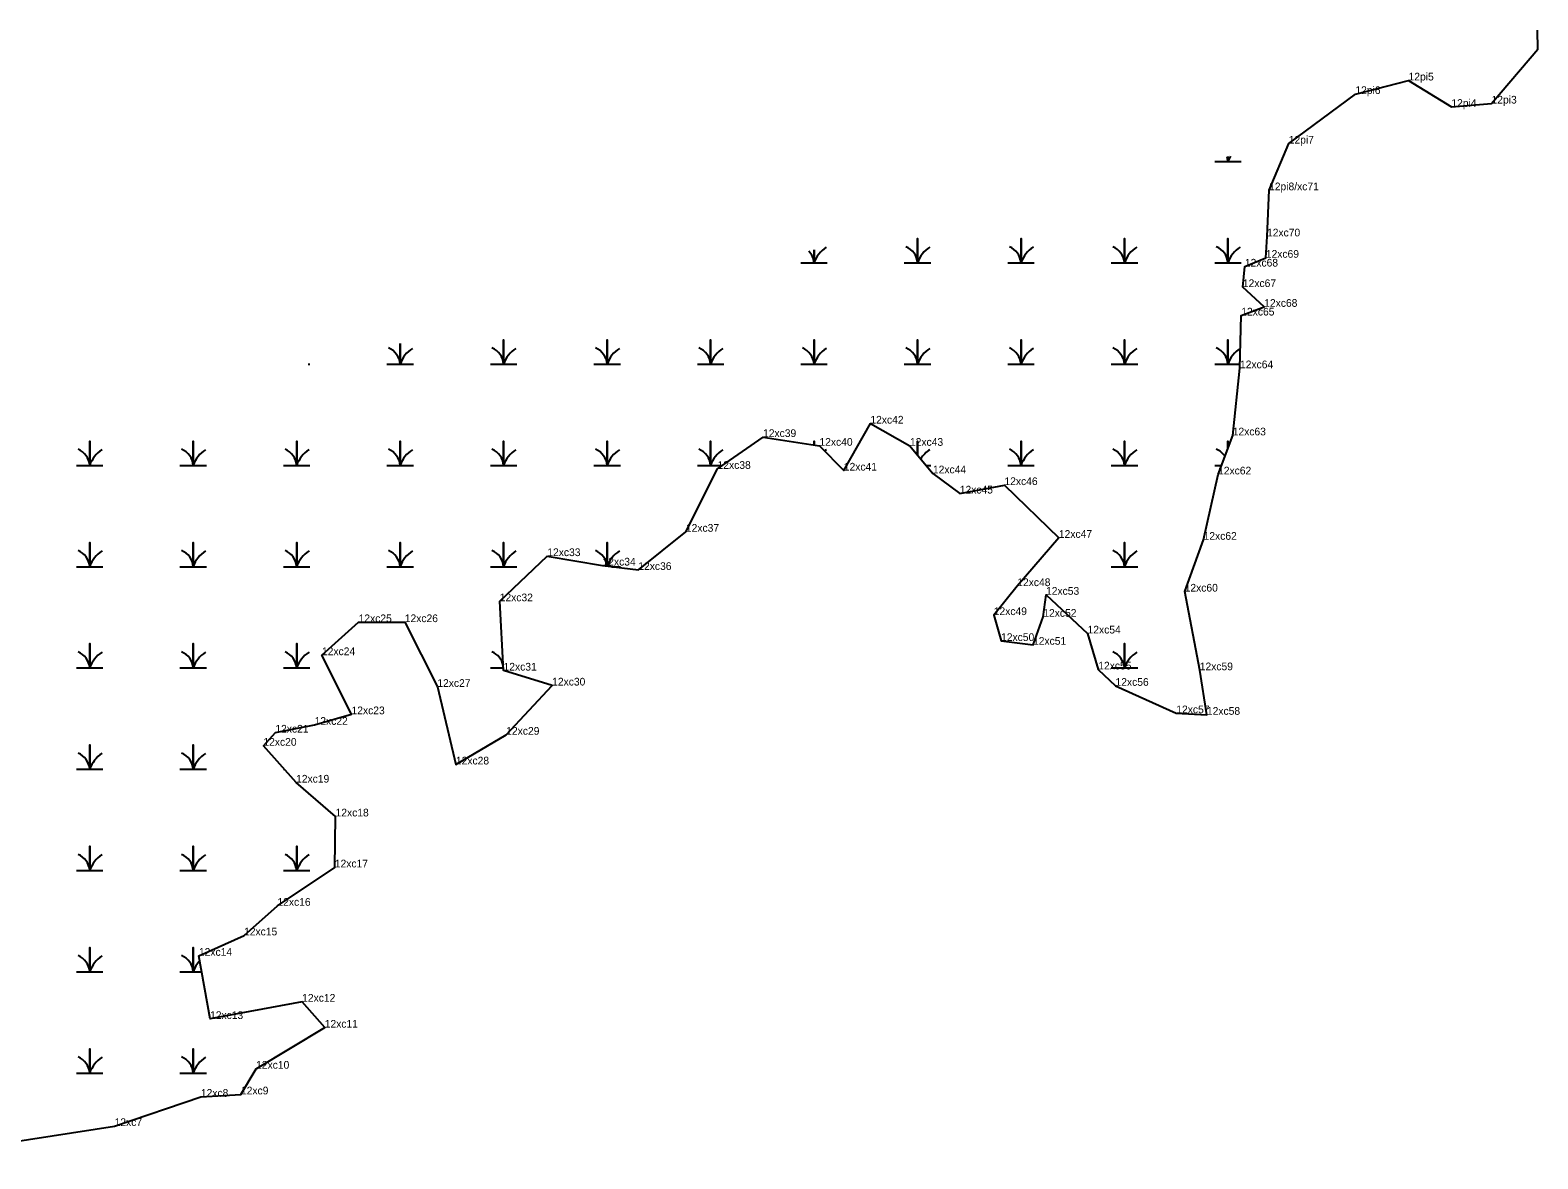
# Model space of a CAD drawing. Extents: x 2072529 to 2268796, y 436423 to 470406.
# Drawn here: x 2230922 to 2231902, y 451635 to 452369 of the extents above; entities that cross this region are included whole.
import ezdxf

# ---------------------------------------------------------------- set-up
doc = ezdxf.new("R2010")
doc.units = 0
for name, color, linetype in [('Exist Environmental Wetland Boundary', 7, 'Continuous'), ('Exist Environmental Wetland Boundary Cogo Comment', 7, 'Continuous'), ('Exist Hydro Swamp or Marsh', 7, 'Continuous'), ('Old_Level_20', 7, 'Continuous')]:
    doc.layers.add(name, color=color, linetype=linetype)

msp = doc.modelspace()

# ---------------------------------------------------------------- linework, layer by layer
at = {"layer": 'Exist Environmental Wetland Boundary'}
msp.add_lwpolyline([(2230840.12, 451635.35), (2230977.33, 451656.68), (2231033.38, 451675.67), (2231059.44, 451677.21), (2231069.29, 451693.9), (2231113.89, 451720.58), (2231099.21, 451737.45), (2231039.34, 451726.21), (2231032.11, 451767.28), (2231061.44, 451780.53), (2231083.15, 451799.77), (2231120.44, 451824.7), (2231120.92, 451857.81), (2231095.26, 451879.8), (2231074.02, 451903.73), (2231081.79, 451912.28), (2231107.3, 451917.34), (2231131.3, 451924.2), (2231112.09, 451962.59), (2231135.92, 451984.02), (2231165.9, 451984.05), (2231187.06, 451941.99), (2231199.13, 451891.58), (2231231.84, 451910.9), (2231261.68, 451942.87), (2231230.1, 451952.58), (2231227.61, 451997.6), (2231258.54, 452026.96), (2231294.4, 452020.83), (2231317.69, 452017.96), (2231348.61, 452042.78), (2231369.19, 452083.62), (2231398.74, 452104.33), (2231435.4, 452098.64), (2231451.23, 452082.52), (2231468.5, 452113.06), (2231494.24, 452098.62), (2231509.15, 452080.73), (2231526.59, 452067.62), (2231555.64, 452073.11), (2231591.01, 452038.81), (2231563.97, 452007.45), (2231548.69, 451988.63), (2231553.44, 451971.8), (2231574.2, 451969.37), (2231580.88, 451987.54), (2231582.65, 452001.84), (2231609.65, 451976.67), (2231616.61, 451953.3), (2231627.81, 451942.68), (2231667.33, 451924.84), (2231687.23, 451923.86), (2231682.58, 451952.79), (2231672.76, 452003.9), (2231685.07, 452037.55), (2231694.47, 452080.01), (2231704, 452105.38), (2231708.71, 452148.99), (2231709.55, 452183.27), (2231724.47, 452188.92), (2231710.6, 452201.75), (2231711.89, 452215.08), (2231725.51, 452220.79), (2231726.27, 452234.66), (2231727.61, 452264.64), (2231740.4, 452294.96), (2231783.7, 452327.18), (2231818.27, 452335.98), (2231846.1, 452318.82), (2231872.2, 452320.98), (2231902.29, 452356.34), (2231902.14, 452368.66)], dxfattribs=at)
at = {"layer": 'Exist Hydro Swamp or Marsh'}
for points in [[(2231692.3, 452283.29), (2231700.9, 452283.29), (2231700.9, 452286.5)], [(2231700.9, 452286.5), (2231700.9, 452283.29), (2231709.5, 452283.29)], [(2231490.55, 452217.49), (2231499.15, 452217.49), (2231499.15, 452233.27), (2231499.15, 452217.49), (2231507.75, 452217.49)], [(2231557.8, 452217.49), (2231566.4, 452217.49), (2231566.4, 452233.27), (2231566.4, 452217.49), (2231575, 452217.49)], [(2231625.05, 452217.49), (2231633.65, 452217.49), (2231633.65, 452233.27), (2231633.65, 452217.49), (2231642.25, 452217.49)], [(2231692.3, 452217.49), (2231700.9, 452217.49), (2231700.9, 452233.27), (2231700.9, 452217.49), (2231709.5, 452217.49)], [(2231423.3, 452217.49), (2231431.9, 452217.49), (2231431.9, 452225.84)], [(2231431.9, 452225.84), (2231431.9, 452217.49), (2231440.5, 452217.49)], [(2231154.3, 452151.69), (2231162.9, 452151.69), (2231162.9, 452165.17)], [(2231162.9, 452165.17), (2231162.9, 452151.69), (2231171.5, 452151.69)], [(2231221.55, 452151.69), (2231230.15, 452151.69), (2231230.15, 452167.47), (2231230.15, 452151.69), (2231238.75, 452151.69)], [(2231288.8, 452151.69), (2231297.4, 452151.69), (2231297.4, 452167.47), (2231297.4, 452151.69), (2231306, 452151.69)], [(2231356.05, 452151.69), (2231364.65, 452151.69), (2231364.65, 452167.47), (2231364.65, 452151.69), (2231373.25, 452151.69)], [(2231423.3, 452151.69), (2231431.9, 452151.69), (2231431.9, 452167.47), (2231431.9, 452151.69), (2231440.5, 452151.69)], [(2231490.55, 452151.69), (2231499.15, 452151.69), (2231499.15, 452167.47), (2231499.15, 452151.69), (2231507.75, 452151.69)], [(2231557.8, 452151.69), (2231566.4, 452151.69), (2231566.4, 452167.47), (2231566.4, 452151.69), (2231575, 452151.69)], [(2231625.05, 452151.69), (2231633.65, 452151.69), (2231633.65, 452167.47), (2231633.65, 452151.69), (2231642.25, 452151.69)], [(2231692.3, 452151.69), (2231700.9, 452151.69), (2231700.9, 452167.47), (2231700.9, 452151.69), (2231708.77, 452151.69)], [(2231103.12, 452151.69), (2231104.25, 452151.69)], [(2230952.55, 452085.89), (2230961.15, 452085.89), (2230961.15, 452101.67), (2230961.15, 452085.89), (2230969.75, 452085.89)], [(2231019.8, 452085.89), (2231028.4, 452085.89), (2231028.4, 452101.67), (2231028.4, 452085.89), (2231037, 452085.89)], [(2231087.05, 452085.89), (2231095.65, 452085.89), (2231095.65, 452101.67), (2231095.65, 452085.89), (2231104.25, 452085.89)], [(2231154.3, 452085.89), (2231162.9, 452085.89), (2231162.9, 452101.67), (2231162.9, 452085.89), (2231171.5, 452085.89)], [(2231221.55, 452085.89), (2231230.15, 452085.89), (2231230.15, 452101.67), (2231230.15, 452085.89), (2231238.75, 452085.89)], [(2231288.8, 452085.89), (2231297.4, 452085.89), (2231297.4, 452101.67), (2231297.4, 452085.89), (2231306, 452085.89)], [(2231356.05, 452085.89), (2231364.65, 452085.89), (2231364.65, 452101.67), (2231364.65, 452085.89), (2231372.43, 452085.89)], [(2231431.9, 452099.19), (2231431.9, 452101.67), (2231431.9, 452099.19)], [(2231499.15, 452092.73), (2231499.15, 452101.67), (2231499.15, 452092.73)], [(2231557.8, 452085.89), (2231566.4, 452085.89), (2231566.4, 452101.67), (2231566.4, 452085.89), (2231575, 452085.89)], [(2231625.05, 452085.89), (2231633.65, 452085.89), (2231633.65, 452101.67), (2231633.65, 452085.89), (2231642.25, 452085.89)], [(2231700.9, 452097.13), (2231700.9, 452101.67), (2231700.9, 452097.13)], [(2231504.85, 452085.89), (2231507.75, 452085.89)], [(2231692.3, 452085.89), (2231696.68, 452085.89)], [(2230952.55, 452020.09), (2230961.15, 452020.09), (2230961.15, 452035.87), (2230961.15, 452020.09), (2230969.75, 452020.09)], [(2231019.8, 452020.09), (2231028.4, 452020.09), (2231028.4, 452035.87), (2231028.4, 452020.09), (2231037, 452020.09)], [(2231087.05, 452020.09), (2231095.65, 452020.09), (2231095.65, 452035.87), (2231095.65, 452020.09), (2231104.25, 452020.09)], [(2231154.3, 452020.09), (2231162.9, 452020.09), (2231162.9, 452035.87), (2231162.9, 452020.09), (2231171.5, 452020.09)], [(2231221.55, 452020.09), (2231230.15, 452020.09), (2231230.15, 452035.87), (2231230.15, 452020.09), (2231238.75, 452020.09)], [(2231297.4, 452020.46), (2231297.4, 452035.87), (2231297.4, 452020.46)], [(2231625.05, 452020.09), (2231633.65, 452020.09), (2231633.65, 452035.87), (2231633.65, 452020.09), (2231642.25, 452020.09)], [(2231300.38, 452020.09), (2231306, 452020.09)], [(2231574.87, 452020.09), (2231575, 452020.09)], [(2230952.55, 451954.29), (2230961.15, 451954.29), (2230961.15, 451970.07), (2230961.15, 451954.29), (2230969.75, 451954.29)], [(2231019.8, 451954.29), (2231028.4, 451954.29), (2231028.4, 451970.07), (2231028.4, 451954.29), (2231037, 451954.29)], [(2231087.05, 451954.29), (2231095.65, 451954.29), (2231095.65, 451970.07), (2231095.65, 451954.29), (2231104.25, 451954.29)], [(2231625.05, 451954.29), (2231633.65, 451954.29), (2231633.65, 451970.07), (2231633.65, 451954.29), (2231642.25, 451954.29)], [(2231221.55, 451954.29), (2231230, 451954.29)], [(2230952.55, 451888.49), (2230961.15, 451888.49), (2230961.15, 451904.27), (2230961.15, 451888.49), (2230969.75, 451888.49)], [(2231019.8, 451888.49), (2231028.4, 451888.49), (2231028.4, 451904.27), (2231028.4, 451888.49), (2231037, 451888.49)], [(2231087.05, 451888.49), (2231087.54, 451888.49)], [(2230952.55, 451822.69), (2230961.15, 451822.69), (2230961.15, 451838.47), (2230961.15, 451822.69), (2230969.75, 451822.69)], [(2231019.8, 451822.69), (2231028.4, 451822.69), (2231028.4, 451838.47), (2231028.4, 451822.69), (2231037, 451822.69)], [(2231087.05, 451822.69), (2231095.65, 451822.69), (2231095.65, 451838.47), (2231095.65, 451822.69), (2231104.25, 451822.69)], [(2230952.55, 451756.89), (2230961.15, 451756.89), (2230961.15, 451772.67), (2230961.15, 451756.89), (2230969.75, 451756.89)], [(2231019.8, 451756.89), (2231028.4, 451756.89), (2231028.4, 451772.67), (2231028.4, 451756.89), (2231033.94, 451756.89)], [(2230952.55, 451691.09), (2230961.15, 451691.09), (2230961.15, 451706.87), (2230961.15, 451691.09), (2230969.75, 451691.09)], [(2231019.8, 451691.09), (2231028.4, 451691.09), (2231028.4, 451706.87), (2231028.4, 451691.09), (2231037, 451691.09)]]:
    msp.add_lwpolyline(points, dxfattribs=at)
for centre, radius, start, end in [((2231688.63, 452282.4), 12.3, 4.14034, 18.7832), ((2231719.14, 452277.23), 19.22, 149.91531, 161.62219), ((2231450.14, 452211.43), 19.22, 122.66671, 161.62219), ((2231486.88, 452216.6), 12.3, 4.14034, 67.53497), ((2231517.39, 452211.43), 19.22, 122.12745, 161.62219), ((2231554.13, 452216.6), 12.3, 4.14034, 67.53497), ((2231584.64, 452211.43), 19.22, 122.12745, 161.62219), ((2231621.38, 452216.6), 12.3, 4.14034, 67.53497), ((2231651.89, 452211.43), 19.22, 122.12745, 161.62219), ((2231688.63, 452216.6), 12.3, 4.14034, 67.53497), ((2231719.14, 452211.43), 19.22, 122.12745, 161.62219), ((2231419.63, 452216.6), 12.3, 4.14034, 43.5807), ((2231150.63, 452150.8), 12.3, 4.14034, 67.53497), ((2231181.14, 452145.63), 19.22, 122.12745, 161.62219), ((2231217.88, 452150.8), 12.3, 4.14034, 67.53497), ((2231248.39, 452145.63), 19.22, 122.12745, 161.62219), ((2231285.13, 452150.8), 12.3, 4.14034, 67.53497), ((2231315.64, 452145.63), 19.22, 122.12745, 161.62219), ((2231352.38, 452150.8), 12.3, 4.14034, 67.53497), ((2231382.89, 452145.63), 19.22, 122.12745, 161.62219), ((2231419.63, 452150.8), 12.3, 4.14034, 67.53497), ((2231450.14, 452145.63), 19.22, 122.12745, 161.62219), ((2231486.88, 452150.8), 12.3, 4.14034, 67.53497), ((2231517.39, 452145.63), 19.22, 122.12745, 161.62219), ((2231554.13, 452150.8), 12.3, 4.14034, 67.53497), ((2231584.64, 452145.63), 19.22, 122.12745, 161.62219), ((2231621.38, 452150.8), 12.3, 4.14034, 67.53497), ((2231651.89, 452145.63), 19.22, 122.12745, 161.62219), ((2231688.63, 452150.8), 12.3, 4.14034, 67.53497), ((2231719.14, 452145.63), 19.22, 122.12745, 161.62219), ((2230948.88, 452085), 12.3, 4.14034, 67.53497), ((2230979.39, 452079.83), 19.22, 122.12745, 161.62219), ((2231016.13, 452085), 12.3, 4.14034, 67.53497), ((2231046.64, 452079.83), 19.22, 122.12745, 161.62219), ((2231083.38, 452085), 12.3, 4.14034, 67.53497), ((2231113.89, 452079.83), 19.22, 122.12745, 161.62219), ((2231150.63, 452085), 12.3, 4.14034, 67.53497), ((2231181.14, 452079.83), 19.22, 122.12745, 161.62219), ((2231217.88, 452085), 12.3, 4.14034, 67.53497), ((2231248.39, 452079.83), 19.22, 122.12745, 161.62219), ((2231285.13, 452085), 12.3, 4.14034, 67.53497), ((2231315.64, 452079.83), 19.22, 122.12745, 161.62219), ((2231352.38, 452085), 12.3, 4.14034, 67.53497), ((2231382.89, 452079.83), 19.22, 122.12745, 161.62219), ((2231450.14, 452079.83), 19.22, 122.12745, 126.52553), ((2231517.39, 452079.83), 19.22, 122.12745, 147.23616), ((2231554.13, 452085), 12.3, 4.14034, 67.53497), ((2231584.64, 452079.83), 19.22, 122.12745, 161.62219), ((2231621.38, 452085), 12.3, 4.14034, 67.53497), ((2231651.89, 452079.83), 19.22, 122.12745, 161.62219), ((2231688.63, 452085), 12.3, 33.46796, 67.53497), ((2230948.88, 452019.2), 12.3, 4.14034, 67.53497), ((2230979.39, 452014.03), 19.22, 122.12745, 161.62219), ((2231016.13, 452019.2), 12.3, 4.14034, 67.53497), ((2231046.64, 452014.03), 19.22, 122.12745, 161.62219), ((2231083.38, 452019.2), 12.3, 4.14034, 67.53497), ((2231113.89, 452014.03), 19.22, 122.12745, 161.62219), ((2231150.63, 452019.2), 12.3, 4.14034, 67.53497), ((2231181.14, 452014.03), 19.22, 122.12745, 161.62219), ((2231217.88, 452019.2), 12.3, 4.14034, 67.53497), ((2231248.39, 452014.03), 19.22, 122.12745, 161.62219), ((2231285.13, 452019.2), 12.3, 5.87159, 67.53497), ((2231315.64, 452014.03), 19.22, 122.12745, 160.51495), ((2231621.38, 452019.2), 12.3, 4.14034, 67.53497), ((2231651.89, 452014.03), 19.22, 122.12745, 161.62219), ((2230948.88, 451953.4), 12.3, 4.14034, 67.53497), ((2230979.39, 451948.23), 19.22, 122.12745, 161.62219), ((2231016.13, 451953.4), 12.3, 4.14034, 67.53497), ((2231046.64, 451948.23), 19.22, 122.12745, 161.62219), ((2231083.38, 451953.4), 12.3, 4.14034, 67.53497), ((2231113.89, 451948.23), 19.22, 122.12745, 161.62219), ((2231217.88, 451953.4), 12.3, 12.12129, 67.53497), ((2231621.38, 451953.4), 12.3, 4.14034, 67.53497), ((2231651.89, 451948.23), 19.22, 122.12745, 161.62219), ((2230948.88, 451887.6), 12.3, 4.14034, 67.53497), ((2230979.39, 451882.43), 19.22, 122.12745, 161.62219), ((2231016.13, 451887.6), 12.3, 4.14034, 67.53497), ((2231046.64, 451882.43), 19.22, 122.12745, 161.62219), ((2230948.88, 451821.8), 12.3, 4.14034, 67.53497), ((2230979.39, 451816.63), 19.22, 122.12745, 161.62219), ((2231016.13, 451821.8), 12.3, 4.14034, 67.53497), ((2231046.64, 451816.63), 19.22, 122.12745, 161.62219), ((2231083.38, 451821.8), 12.3, 4.14034, 67.53497), ((2231113.89, 451816.63), 19.22, 122.12745, 161.62219), ((2230948.88, 451756), 12.3, 4.14034, 67.53497), ((2230979.39, 451750.83), 19.22, 122.12745, 161.62219), ((2231016.13, 451756), 12.3, 4.14034, 67.53497), ((2231046.64, 451750.83), 19.22, 136.60075, 161.62219), ((2230948.88, 451690.2), 12.3, 4.14034, 67.53497), ((2230979.39, 451685.03), 19.22, 122.12745, 161.62219), ((2231016.13, 451690.2), 12.3, 4.14034, 67.53497), ((2231046.64, 451685.03), 19.22, 122.12745, 161.62219)]:
    msp.add_arc(centre, radius, start, end, dxfattribs=at)
at = {"layer": 'Old_Level_20'}
for p, q in [((2231902.14, 452368.66), (2231902.14, 452368.66)), ((2231902.29, 452356.34), (2231902.29, 452356.34)), ((2231818.27, 452335.98), (2231818.27, 452335.98)), ((2231783.7, 452327.18), (2231783.7, 452327.18)), ((2231846.1, 452318.82), (2231846.1, 452318.82)), ((2231872.2, 452320.98), (2231872.2, 452320.98)), ((2231740.4, 452294.96), (2231740.4, 452294.96)), ((2231727.61, 452264.64), (2231727.61, 452264.64)), ((2231726.27, 452234.66), (2231726.27, 452234.66)), ((2231725.51, 452220.79), (2231725.51, 452220.79)), ((2231711.89, 452215.08), (2231711.89, 452215.08)), ((2231710.6, 452201.75), (2231710.6, 452201.75)), ((2231724.47, 452188.92), (2231724.47, 452188.92)), ((2231709.55, 452183.27), (2231709.55, 452183.27)), ((2231708.71, 452148.99), (2231708.71, 452148.99)), ((2231468.5, 452113.06), (2231468.5, 452113.06)), ((2231398.74, 452104.33), (2231398.74, 452104.33)), ((2231704, 452105.38), (2231704, 452105.38)), ((2231435.4, 452098.64), (2231435.4, 452098.64)), ((2231494.24, 452098.62), (2231494.24, 452098.62)), ((2231369.19, 452083.62), (2231369.19, 452083.62)), ((2231451.23, 452082.52), (2231451.23, 452082.52)), ((2231509.15, 452080.73), (2231509.15, 452080.73)), ((2231694.47, 452080.01), (2231694.47, 452080.01)), ((2231555.64, 452073.11), (2231555.64, 452073.11)), ((2231526.59, 452067.62), (2231526.59, 452067.62)), ((2231348.61, 452042.78), (2231348.61, 452042.78)), ((2231591.01, 452038.81), (2231591.01, 452038.81)), ((2231685.07, 452037.55), (2231685.07, 452037.55)), ((2231258.54, 452026.96), (2231258.54, 452026.96)), ((2231294.4, 452020.83), (2231294.4, 452020.83)), ((2231317.69, 452017.96), (2231317.69, 452017.96)), ((2231563.97, 452007.45), (2231563.97, 452007.45)), ((2231582.65, 452001.84), (2231582.65, 452001.84)), ((2231672.76, 452003.9), (2231672.76, 452003.9)), ((2231227.61, 451997.6), (2231227.61, 451997.6)), ((2231135.92, 451984.02), (2231135.92, 451984.02)), ((2231165.9, 451984.05), (2231165.9, 451984.05)), ((2231548.69, 451988.63), (2231548.69, 451988.63)), ((2231580.88, 451987.54), (2231580.88, 451987.54)), ((2231609.65, 451976.67), (2231609.65, 451976.67)), ((2231112.09, 451962.59), (2231112.09, 451962.59)), ((2231553.44, 451971.8), (2231553.44, 451971.8)), ((2231574.2, 451969.37), (2231574.2, 451969.37)), ((2231230.1, 451952.58), (2231230.1, 451952.58)), ((2231616.61, 451953.3), (2231616.61, 451953.3)), ((2231682.58, 451952.79), (2231682.58, 451952.79)), ((2231261.68, 451942.87), (2231261.68, 451942.87)), ((2231627.81, 451942.68), (2231627.81, 451942.68)), ((2231187.06, 451941.99), (2231187.06, 451941.99)), ((2231131.3, 451924.2), (2231131.3, 451924.2)), ((2231667.33, 451924.84), (2231667.33, 451924.84)), ((2231687.23, 451923.86), (2231687.23, 451923.86)), ((2231107.3, 451917.34), (2231107.3, 451917.34)), ((2231074.02, 451903.73), (2231074.02, 451903.73)), ((2231081.79, 451912.28), (2231081.79, 451912.28)), ((2231231.84, 451910.9), (2231231.84, 451910.9)), ((2231199.13, 451891.58), (2231199.13, 451891.58)), ((2231095.26, 451879.8), (2231095.26, 451879.8)), ((2231120.92, 451857.81), (2231120.92, 451857.81)), ((2231120.44, 451824.7), (2231120.44, 451824.7)), ((2231083.15, 451799.77), (2231083.15, 451799.77)), ((2231061.44, 451780.53), (2231061.44, 451780.53)), ((2231032.11, 451767.28), (2231032.11, 451767.28)), ((2231099.21, 451737.45), (2231099.21, 451737.45)), ((2231039.34, 451726.21), (2231039.34, 451726.21)), ((2231113.89, 451720.58), (2231113.89, 451720.58)), ((2231069.29, 451693.9), (2231069.29, 451693.9)), ((2231033.38, 451675.67), (2231033.38, 451675.67)), ((2231059.44, 451677.21), (2231059.44, 451677.21)), ((2230977.33, 451656.68), (2230977.33, 451656.68))]:
    msp.add_line(p, q, dxfattribs=at)

# ---------------------------------------------------------------- texts
at = {"layer": 'Exist Environmental Wetland Boundary Cogo Comment'}
for s, p in [('12pi5', (2231818.27, 452335.98)), ('12pi6', (2231783.7, 452327.18)), ('12pi3', (2231872.2, 452320.98)), ('12pi4', (2231846.1, 452318.82)), ('12pi7', (2231740.4, 452294.96)), ('12pi8/xc71', (2231727.61, 452264.64)), ('12xc70', (2231726.27, 452234.66)), ('12xc68', (2231711.89, 452215.08)), ('12xc69', (2231725.51, 452220.79)), ('12xc67', (2231710.6, 452201.75)), ('12xc65', (2231709.55, 452183.27)), ('12xc68', (2231724.47, 452188.92)), ('12xc64', (2231708.71, 452148.99)), ('12xc39', (2231398.74, 452104.33)), ('12xc42', (2231468.5, 452113.06)), ('12xc63', (2231704, 452105.38)), ('12xc40', (2231435.4, 452098.64)), ('12xc43', (2231494.24, 452098.62)), ('12xc38', (2231369.19, 452083.62)), ('12xc41', (2231451.23, 452082.52)), ('12xc44', (2231509.15, 452080.73)), ('12xc62', (2231694.47, 452080.01)), ('12xc45', (2231526.59, 452067.62)), ('12xc46', (2231555.64, 452073.11)), ('12xc37', (2231348.61, 452042.78)), ('12xc47', (2231591.01, 452038.81)), ('12xc62', (2231685.07, 452037.55)), ('12xc33', (2231258.54, 452026.96)), ('12xc34', (2231294.4, 452020.83)), ('12xc36', (2231317.69, 452017.96)), ('12xc48', (2231563.97, 452007.45)), ('12xc32', (2231227.61, 451997.6)), ('12xc53', (2231582.65, 452001.84)), ('12xc60', (2231672.76, 452003.9)), ('12xc49', (2231548.69, 451988.63)), ('12xc52', (2231580.88, 451987.54)), ('12xc25', (2231135.92, 451984.02)), ('12xc26', (2231165.9, 451984.05)), ('12xc54', (2231609.65, 451976.67)), ('12xc50', (2231553.44, 451971.8)), ('12xc51', (2231574.2, 451969.37)), ('12xc24', (2231112.09, 451962.59)), ('12xc31', (2231230.1, 451952.58)), ('12xc55', (2231616.61, 451953.3)), ('12xc59', (2231682.58, 451952.79)), ('12xc27', (2231187.06, 451941.99)), ('12xc30', (2231261.68, 451942.87)), ('12xc56', (2231627.81, 451942.68)), ('12xc23', (2231131.3, 451924.2)), ('12xc57', (2231667.33, 451924.84)), ('12xc58', (2231687.23, 451923.86)), ('12xc21', (2231081.79, 451912.28)), ('12xc22', (2231107.3, 451917.34)), ('12xc29', (2231231.84, 451910.9)), ('12xc20', (2231074.02, 451903.73)), ('12xc28', (2231199.13, 451891.58)), ('12xc19', (2231095.26, 451879.8)), ('12xc18', (2231120.92, 451857.81)), ('12xc17', (2231120.44, 451824.7)), ('12xc16', (2231083.15, 451799.77)), ('12xc15', (2231061.44, 451780.53)), ('12xc14', (2231032.11, 451767.28)), ('12xc12', (2231099.21, 451737.45)), ('12xc13', (2231039.34, 451726.21)), ('12xc11', (2231113.89, 451720.58)), ('12xc10', (2231069.29, 451693.9)), ('12xc8', (2231033.38, 451675.67)), ('12xc9', (2231059.44, 451677.21)), ('12xc7', (2230977.33, 451656.68))]:
    msp.add_text(s, height=5, dxfattribs=at).set_placement(p)

doc.saveas('drawing.dxf')
